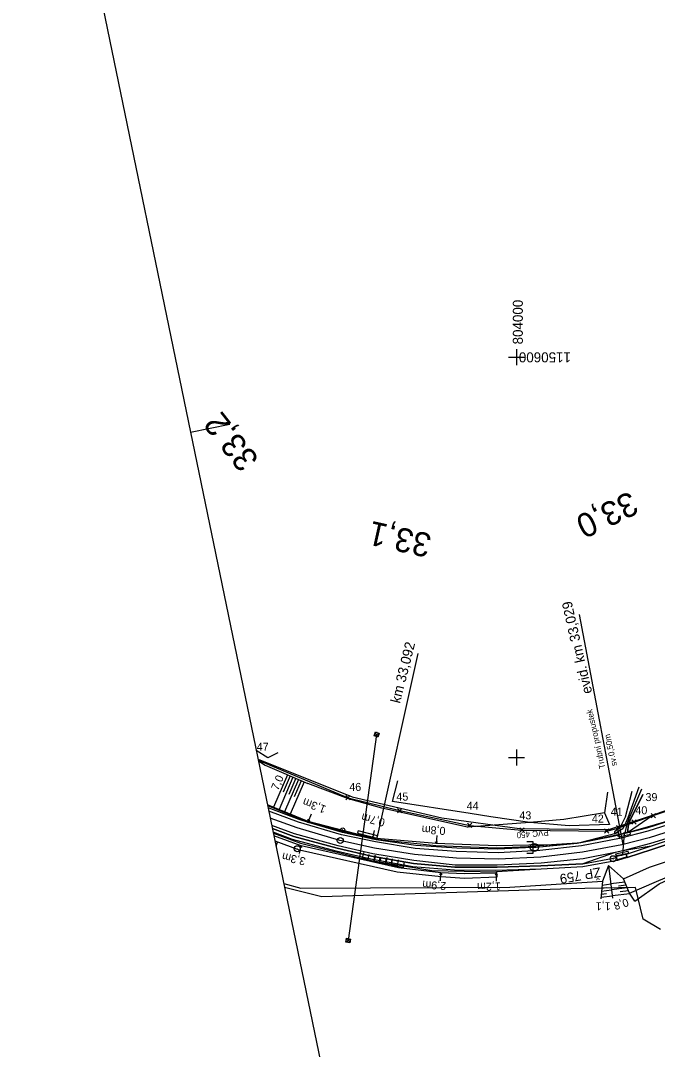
# Model space of a CAD drawing. Extents: x -804166 to -803706, y -1151030 to -1150147.
# Drawn here: x -804123.8 to -803964.8, y -1150773 to -1150515.9 of the extents above; entities that cross this region are included whole.
import ezdxf

# ---------------------------------------------------------------- set-up
doc = ezdxf.new("R2010")
doc.units = 0
for name, color, linetype in [('0381KM032-037P - Vrstva 1', 7, 'Continuous'), ('0381KM032-037P - Vrstva 11', 7, 'Continuous'), ('0381KM032-037P - Vrstva 13', 7, 'Continuous'), ('0381KM032-037P - Vrstva 16', 7, 'Continuous'), ('0381KM032-037P - Vrstva 17', 7, 'Continuous'), ('0381KM032-037P - Vrstva 19', 7, 'Continuous'), ('0381KM032-037P - Vrstva 25', 7, 'Continuous'), ('0381KM032-037P - Vrstva 4', 7, 'Continuous'), ('0381KM032-037P - Vrstva 43', 7, 'Continuous'), ('0381KM032-037P - Vrstva 44', 7, 'Continuous'), ('0381KM032-037P - Vrstva 48', 7, 'Continuous'), ('0381KM032-037P - Vrstva 49', 7, 'Continuous'), ('0381KM032-037P - Vrstva 7', 7, 'Continuous'), ('0381KM032-037P - Vrstva 9', 7, 'Continuous'), ('Default', 7, 'Continuous'), ('formát', 7, 'Continuous'), ('hran DP - hran DP', 7, 'Continuous'), ('krizky_1000 - souradnice', 7, 'Continuous'), ('krizky_1000 - Vrstva 1', 7, 'Continuous'), ('PSR_C2_2_Lomove_body_Vimperk - Vrstva 60', 7, 'Continuous'), ('PSR_C2_2_trasa_Vimperk - Kabelová trasa', 7, 'Continuous'), ('vyt_sit - stávající', 7, 'Continuous')]:
    doc.layers.add(name, color=color, linetype=linetype)

msp = doc.modelspace()

# ---------------------------------------------------------------- linework, layer by layer
at = {"layer": '0381KM032-037P - Vrstva 1'}
msp.add_lwpolyline([(-803901.91, -1150682.6), (-803910.01, -1150690), (-803918.64, -1150696.78), (-803928.04, -1150703.06), (-803937.95, -1150708.69), (-803946.8, -1150712.93), (-803956.66, -1150716.87), (-803966.85, -1150720.1), (-803973.69, -1150721.81), (-803983.51, -1150723.68), (-803993.92, -1150724.91), (-804004.46, -1150725.42), (-804014.95, -1150725.21), (-804025.47, -1150724.25), (-804035.41, -1150722.67), (-804044.08, -1150720.74), (-804054.77, -1150717.61), (-804061.47, -1150715.14)], dxfattribs=at)
at = {"layer": '0381KM032-037P - Vrstva 11'}
for p, q in [((-804034.26, -1150693.99), (-804035.54, -1150694.57)), ((-804034.75, -1150693.8), (-804035.36, -1150694.08)), ((-804034.44, -1150694.48), (-804035.04, -1150694.76)), ((-804041.41, -1150745.38), (-804042.6, -1150746.13)), ((-804041.93, -1150745.26), (-804042.49, -1150745.62)), ((-804041.53, -1150745.9), (-804042.08, -1150746.25))]:
    msp.add_line(p, q, dxfattribs=at)
for points in [[(-804034.6, -1150694.92), (-804035.54, -1150694.57), (-804035.19, -1150693.64), (-804034.25, -1150693.98)], [(-804041.63, -1150746.35), (-804042.61, -1150746.13), (-804042.39, -1150745.16), (-804041.41, -1150745.38)]]:
    msp.add_lwpolyline(points, close=True, dxfattribs=at)
at = {"layer": '0381KM032-037P - Vrstva 13'}
for p, q in [((-804051.27, -1150714.14), (-804052.03, -1150715.99)), ((-804035.82, -1150720.44), (-804051.93, -1150716.22)), ((-804035.5, -1150718.26), (-804035.97, -1150720.21)), ((-804019.87, -1150719.5), (-804020.03, -1150721.49)), ((-804054.2, -1150724.02), (-804053.75, -1150722.07)), ((-803972.34, -1150724.85), (-803974.74, -1150725.59)), ((-803972.54, -1150724.23), (-803972.54, -1150724.26)), ((-803972.54, -1150724.26), (-803972.29, -1150725.01)), ((-803972.34, -1150724.85), (-803972.29, -1150725.01)), ((-803974.7, -1150725.77), (-803974.91, -1150725)), ((-803974.74, -1150725.59), (-803974.7, -1150725.77)), ((-803972.29, -1150725.01), (-803974.7, -1150725.77)), ((-804018.95, -1150730.84), (-804018.83, -1150728.85)), ((-804004.99, -1150728.9), (-804004.87, -1150729.93)), ((-804004.95, -1150730.9), (-804004.99, -1150728.9))]:
    msp.add_line(p, q, dxfattribs=at)
for points in [[(-803902.54, -1150686.99), (-803908.53, -1150691.68), (-803917.54, -1150698.65), (-803926.89, -1150705.06), (-803937, -1150710.49), (-803946.02, -1150714.66), (-803956.26, -1150718.85), (-803966.29, -1150722.19), (-803972.54, -1150724.26)], [(-803972.29, -1150725.01), (-803966.12, -1150722.97), (-803955.96, -1150719.58), (-803945.71, -1150715.38), (-803936.57, -1150711.19), (-803926.51, -1150705.78), (-803917.07, -1150699.31), (-803908.04, -1150692.29), (-803902.09, -1150687.65)], [(-804052.03, -1150715.99), (-804062.15, -1150711.83)], [(-804062.12, -1150712.02), (-804052.3, -1150716.03), (-804051.93, -1150716.22)], [(-804052.11, -1150715.42), (-804052.03, -1150715.99), (-804051.56, -1150715.64)], [(-803991.2, -1150721.8), (-803996.89, -1150721.92), (-804004.84, -1150722.06), (-804020.03, -1150721.49), (-804035.97, -1150720.21), (-804052.03, -1150715.99)], [(-804060.92, -1150717.79), (-804055.61, -1150719.76), (-804044.75, -1150722.66), (-804036.16, -1150724.67), (-804025.7, -1150726.54), (-804015.38, -1150727.38), (-804004.78, -1150727.4), (-803993.85, -1150727.11), (-803983.42, -1150726.57), (-803974.91, -1150725)], [(-803974.7, -1150725.77), (-803983.37, -1150727.37), (-803993.84, -1150727.91), (-804005.29, -1150728.22), (-804015.43, -1150728.15), (-804025.86, -1150727.31), (-804036.32, -1150725.46), (-804045.02, -1150723.43), (-804055.91, -1150720.49), (-804060.73, -1150718.71)], [(-804060.69, -1150718.95), (-804053.9, -1150721.4), (-804036.64, -1150725.7), (-804021.1, -1150728.28), (-804004.99, -1150728.61), (-804004.87, -1150729.93)], [(-804004.99, -1150728.9), (-804013.04, -1150729.07), (-804018.83, -1150728.85), (-804029.4, -1150727.62), (-804053.75, -1150722.07), (-804060.56, -1150719.58)], [(-804036.15, -1150719.65), (-804035.97, -1150720.21), (-804035.56, -1150719.79)], [(-804004.87, -1150729.93), (-804012.98, -1150730.26), (-804018.76, -1150729.81), (-804029.79, -1150728.64), (-804054.15, -1150723.15), (-804060.27, -1150720.94)], [(-804053.57, -1150722.62), (-804053.75, -1150722.07), (-804054.16, -1150722.49)], [(-803991.2, -1150721.8), (-803997.06, -1150722.33), (-804004.97, -1150722.65), (-804020.12, -1150722.09), (-804035.82, -1150720.44)], [(-804020.29, -1150720.97), (-804020.03, -1150721.49), (-804019.69, -1150721.02)], [(-803972.34, -1150724.85), (-803972.34, -1150724.85), (-803972.48, -1150724.42), (-803972.48, -1150724.42), (-803972.54, -1150724.26), (-803972.54, -1150724.23)], [(-803974.74, -1150725.59), (-803974.75, -1150725.58), (-803974.86, -1150725.17), (-803974.86, -1150725.17), (-803974.91, -1150725)], [(-804018.56, -1150729.36), (-804018.83, -1150728.85), (-804019.16, -1150729.33)], [(-804004.68, -1150729.4), (-804004.99, -1150728.9), (-804005.28, -1150729.41)], [(-804004.99, -1150728.9), (-804004.99, -1150728.9), (-804004.99, -1150728.9), (-804004.99, -1150728.61)]]:
    msp.add_lwpolyline(points, dxfattribs=at)
at = {"layer": '0381KM032-037P - Vrstva 16'}
msp.add_line((-803972.81, -1150718.81), (-803972.25, -1150718.74), dxfattribs=at)
for points in [[(-803969.39, -1150707.42), (-803972.15, -1150715.07), (-803972.68, -1150716.27), (-803973.1, -1150717.09), (-803973.4, -1150717.86), (-803975.59, -1150719.16)], [(-803971.15, -1150708.54), (-803972.82, -1150714.95), (-803974.15, -1150717.57), (-803975.48, -1150718.61), (-803975.59, -1150719.16)], [(-803972.81, -1150718.81), (-803972.31, -1150716.69), (-803971.8, -1150715.26), (-803968.63, -1150707.87)], [(-803968.41, -1150709.25), (-803971.62, -1150715.84), (-803971.99, -1150716.8), (-803972.25, -1150718.74)]]:
    msp.add_lwpolyline(points, dxfattribs=at)
at = {"layer": '0381KM032-037P - Vrstva 17'}
for points in [[(-804059.54, -1150698.86), (-804062.04, -1150700.07), (-804064.95, -1150698.29)], [(-803996.63, -1150716.3), (-804006.34, -1150714.83), (-804011.55, -1150713.97), (-804030.97, -1150711.02), (-804029.61, -1150705.83)], [(-803977.22, -1150708.65), (-803977.99, -1150713.83)], [(-803977.99, -1150713.83), (-803976.74, -1150716.79), (-803986.83, -1150717.08), (-803996.63, -1150716.3)]]:
    msp.add_lwpolyline(points, dxfattribs=at)
at = {"layer": '0381KM032-037P - Vrstva 19'}
for p, q in [((-803973.32, -1150721.76), (-803984.23, -1150664.27)), ((-803971.53, -1150718.65), (-803974.65, -1150719.35)), ((-803974.65, -1150719.35), (-803974.64, -1150719.23)), ((-803974.51, -1150719.84), (-803974.65, -1150719.35)), ((-803974.51, -1150719.84), (-803971.47, -1150719.15)), ((-803973.09, -1150718.93), (-803973.51, -1150724.35)), ((-803972.25, -1150718.74), (-803972.81, -1150718.81)), ((-803971.47, -1150719.15), (-803971.53, -1150718.65)), ((-803975.23, -1150724.05), (-803972.11, -1150723.39)), ((-803975.23, -1150724.05), (-803975.1, -1150724.59)), ((-803972.01, -1150723.98), (-803975.1, -1150724.59)), ((-803974.91, -1150725), (-803975.1, -1150724.59)), ((-803974.91, -1150725), (-803974.9, -1150724.64)), ((-803972.11, -1150723.39), (-803972.01, -1150723.98)), ((-803974.91, -1150725), (-803974.91, -1150725))]:
    msp.add_line(p, q, dxfattribs=at)
for points in [[(-803974.64, -1150719.23), (-803973.09, -1150718.93), (-803972.81, -1150718.81)], [(-803975.1, -1150724.59), (-803974.9, -1150724.64), (-803973.51, -1150724.35), (-803972.67, -1150724.15), (-803972.01, -1150723.98)]]:
    msp.add_lwpolyline(points, dxfattribs=at)
for centre, major_axis, ratio, start_param, end_param in [((-803973.07, -1150718.94), (-0.255, -0.028), 0.056503, 4.768181, 7.86041), ((-803973.09, -1150718.94), (-0.255, -0.028), 0.056457, 1.624991, 4.720578), ((-803973.51, -1150724.33), (0.232, 0.091), 0.052847, 1.520766, 4.668999), ((-803973.51, -1150724.33), (0.232, 0.091), 0.052921, 4.661932, 7.811186)]:
    msp.add_ellipse(centre, major_axis=major_axis, ratio=ratio, start_param=start_param, end_param=end_param, dxfattribs=at)
at = {"layer": '0381KM032-037P - Vrstva 25'}
msp.add_line((-804034.9, -1150694.28), (-804042.01, -1150745.75), dxfattribs=at)
at = {"layer": '0381KM032-037P - Vrstva 4'}
msp.add_line((-803966.29, -1150722.19), (-803973.38, -1150723.34), dxfattribs=at)
for points in [[(-803904.89, -1150683), (-803906.52, -1150683.39), (-803911.52, -1150688.07), (-803920.11, -1150694.83), (-803929.41, -1150700.94), (-803939.16, -1150706.21), (-803947.89, -1150710.4), (-803957.6, -1150714.53), (-803967.41, -1150717.64)], [(-803904.89, -1150683), (-803911.05, -1150688.74), (-803919.71, -1150695.38), (-803929.09, -1150701.48), (-803938.79, -1150707.1), (-803947.48, -1150711.34), (-803957.42, -1150715.32), (-803967.18, -1150718.43)], [(-803902.5, -1150685.47), (-803908.94, -1150691.19), (-803917.69, -1150697.99), (-803927.24, -1150704.35), (-803937.2, -1150710.05), (-803946.25, -1150714.3), (-803956.41, -1150718.42), (-803966.45, -1150721.53)], [(-803902.5, -1150685.47), (-803902.54, -1150686.99), (-803908.53, -1150691.68), (-803917.54, -1150698.65), (-803926.89, -1150705.06), (-803937, -1150710.49), (-803946.02, -1150714.66), (-803956.26, -1150718.85), (-803966.29, -1150722.19)], [(-803967.41, -1150717.64), (-803975.82, -1150719.77), (-803983.88, -1150721.36), (-803994.18, -1150722.4), (-804004.64, -1150722.95), (-804014.86, -1150722.69), (-804025.14, -1150721.99), (-804034.98, -1150720.62), (-804043.41, -1150718.77), (-804051.93, -1150716.22), (-804054.24, -1150715.48), (-804062, -1150712.59)], [(-803967.18, -1150718.43), (-803974.22, -1150720.27), (-803983.73, -1150722.13), (-803994.13, -1150723.26), (-804004.52, -1150723.87), (-804015.05, -1150723.54), (-804025.27, -1150722.78), (-804035.17, -1150721.13), (-804043.67, -1150719.32), (-804054.39, -1150716.19), (-804061.83, -1150713.39)], [(-803966.45, -1150721.53), (-803973.38, -1150723.34), (-803975.35, -1150723.79), (-803983.32, -1150725.37), (-803993.82, -1150726.43), (-804004.8, -1150726.96), (-804015.29, -1150726.92), (-804025.6, -1150725.76), (-804035.88, -1150724.11), (-804044.5, -1150722.13), (-804055.4, -1150719.07), (-804061.09, -1150716.98)], [(-803975.35, -1150723.79), (-803983.42, -1150726.57), (-803993.85, -1150727.11), (-804004.78, -1150727.4), (-804015.38, -1150727.38), (-804025.7, -1150726.54), (-804036.16, -1150724.67), (-804044.75, -1150722.66), (-804055.61, -1150719.76), (-804060.92, -1150717.79)]]:
    msp.add_lwpolyline(points, dxfattribs=at)
at = {"layer": '0381KM032-037P - Vrstva 43'}
for points in [[(-803972.71, -1150719.94), (-803974.19, -1150720.21), (-803974.72, -1150717.26), (-803973.25, -1150716.99)], [(-803997.39, -1150721.01), (-803995.89, -1150721.01), (-803995.89, -1150724.01), (-803997.39, -1150724.01)], [(-804035.17, -1150724.55), (-804035.58, -1150726), (-804038.46, -1150725.19), (-804038.06, -1150723.74)], [(-804033.84, -1150725), (-804034.23, -1150726.45), (-804037.12, -1150725.67), (-804036.73, -1150724.22)], [(-804032.32, -1150725.04), (-804032.63, -1150726.51), (-804035.56, -1150725.9), (-804035.26, -1150724.43)], [(-804031.05, -1150725.35), (-804031.24, -1150726.84), (-804034.22, -1150726.45), (-804034.02, -1150724.96)], [(-804029.49, -1150725.62), (-804029.77, -1150727.09), (-804032.72, -1150726.52), (-804032.43, -1150725.05)], [(-804028.05, -1150726.05), (-804028.31, -1150727.53), (-804031.27, -1150727.01), (-804031.01, -1150725.53)]]:
    msp.add_lwpolyline(points, dxfattribs=at)
msp.add_circle((-803995.51, -1150722.5), 1, dxfattribs=at)
at = {"layer": '0381KM032-037P - Vrstva 44'}
msp.add_lwpolyline([(-803995.89, -1150722.51), (-803984.82, -1150721.44), (-803974.46, -1150718.74)], dxfattribs=at)
at = {"layer": '0381KM032-037P - Vrstva 48'}
for p, q in [((-804057.18, -1150704.34), (-804060.65, -1150712.45)), ((-804055.8, -1150704.93), (-804059.26, -1150713.02)), ((-804056.49, -1150704.63), (-804058.22, -1150708.69)), ((-804054.42, -1150705.52), (-804057.88, -1150713.59)), ((-804055.11, -1150705.22), (-804056.84, -1150709.27)), ((-804053.04, -1150706.11), (-804056.49, -1150714.16)), ((-804053.73, -1150705.81), (-804055.46, -1150709.84)), ((-804060.03, -1150722.14), (-804059.67, -1150721.16)), ((-803978.65, -1150732.65), (-803977.48, -1150732.51)), ((-803978.58, -1150731.89), (-803976.4, -1150731.62)), ((-803972.9, -1150731.19), (-803976.4, -1150731.62)), ((-803972.3, -1150732.62), (-803976.22, -1150733.11)), ((-803972.6, -1150731.91), (-803974.46, -1150732.13)), ((-803978.85, -1150734.94), (-803976.04, -1150734.6)), ((-803978.79, -1150734.18), (-803977.46, -1150734.02)), ((-803978.72, -1150733.42), (-803976.22, -1150733.11)), ((-803971.67, -1150734.06), (-803976.04, -1150734.6)), ((-803972, -1150733.34), (-803974.07, -1150733.6))]:
    msp.add_line(p, q, dxfattribs=at)
at = {"layer": '0381KM032-037P - Vrstva 49'}
for p, q in [((-803976.97, -1150726.99), (-803978.5, -1150730.91)), ((-803976.97, -1150726.99), (-803975.97, -1150735.13)), ((-803976.97, -1150726.99), (-803973.24, -1150730.36)), ((-804001.62, -1150732.39), (-803978.5, -1150730.91)), ((-803978.5, -1150730.91), (-803978.89, -1150735.31))]:
    msp.add_line(p, q, dxfattribs=at)
for points in [[(-803984.82, -1150721.44), (-803974.64, -1150719.23), (-803973.09, -1150718.93), (-803972.81, -1150718.81), (-803972.25, -1150718.74), (-803965.21, -1150716.75), (-803957.6, -1150714.53), (-803947.89, -1150710.4), (-803939.16, -1150706.21), (-803931.83, -1150702.12), (-803924.09, -1150697.22), (-803916.61, -1150691.84), (-803910.08, -1150686.51), (-803906.52, -1150683.39), (-803903.6, -1150681.32)], [(-803972.25, -1150718.74), (-803965.84, -1150714.34), (-803956.6, -1150711.22), (-803948.84, -1150707.73), (-803941.39, -1150704.08), (-803932.78, -1150700.06), (-803925.79, -1150694.95), (-803918.15, -1150689.68), (-803911.55, -1150684.9), (-803903.6, -1150681.32)], [(-803902.09, -1150687.65), (-803908.04, -1150692.29), (-803917.07, -1150699.31), (-803926.51, -1150705.78), (-803936.57, -1150711.19), (-803945.71, -1150715.38), (-803955.96, -1150719.58), (-803966.12, -1150722.97), (-803972.29, -1150725.01), (-803974.7, -1150725.77), (-803983.37, -1150727.37), (-803993.84, -1150727.91), (-804004.99, -1150728.61), (-804004.87, -1150729.93), (-804012.98, -1150730.26), (-804018.76, -1150729.81), (-804029.79, -1150728.64), (-804054.15, -1150723.15), (-804060.27, -1150720.94)], [(-803973.24, -1150730.36), (-803966.72, -1150727.46), (-803955.16, -1150723.59), (-803942.54, -1150718.42), (-803927.91, -1150711.46), (-803917.77, -1150704.05), (-803910.65, -1150697.21), (-803903.52, -1150690.49), (-803900.1, -1150686.57)], [(-803970.39, -1150735.93), (-803964.35, -1150731.61), (-803955.1, -1150727.23), (-803941.08, -1150721.95), (-803928.21, -1150715.68), (-803916.07, -1150708.06), (-803913.5, -1150704.53), (-803910.65, -1150697.21)], [(-804064.42, -1150700.87), (-804062.72, -1150701.97), (-804052.08, -1150706.52)], [(-803977.22, -1150708.65), (-803977.99, -1150713.83), (-803988.17, -1150715.55), (-803996.63, -1150716.3), (-804012.18, -1150717.41), (-804033.61, -1150712.69), (-804041.95, -1150710.32), (-804052.08, -1150706.52)], [(-803971.76, -1150733.92), (-803964.99, -1150730.97), (-803955.15, -1150726.85), (-803941.3, -1150721.62), (-803928.58, -1150715.41), (-803917.05, -1150707.62), (-803913.5, -1150704.53)], [(-803972.25, -1150718.74), (-803971.99, -1150716.8), (-803971.62, -1150715.84), (-803968.41, -1150709.25)], [(-804062.15, -1150711.83), (-804052.03, -1150715.99)], [(-803984.82, -1150721.44), (-803991.2, -1150721.8), (-803996.89, -1150721.92), (-804004.84, -1150722.06), (-804020.03, -1150721.49), (-804035.97, -1150720.21), (-804052.03, -1150715.99)], [(-804058.09, -1150731.52), (-804053.81, -1150732.63), (-804001.62, -1150732.39)], [(-803970.39, -1150735.93), (-803971.76, -1150733.92), (-803973.24, -1150730.36)]]:
    msp.add_lwpolyline(points, dxfattribs=at)
at = {"layer": '0381KM032-037P - Vrstva 7'}
msp.add_line((-804043.32, -1150718.13), (-804043.42, -1150718.1), dxfattribs=at)
for centre, radius in [((-804043.37, -1150718.12), 0.5), ((-804043.99, -1150720.76), 0.75)]:
    msp.add_circle(centre, radius, dxfattribs=at)
at = {"layer": '0381KM032-037P - Vrstva 9'}
for p, q in [((-804034.8, -1150720.15), (-804024.5, -1150674.02)), ((-804039.51, -1150718.34), (-804039.66, -1150718.92)), ((-804039.66, -1150718.92), (-804034.81, -1150720.14)), ((-804034.66, -1150719.56), (-804039.51, -1150718.34)), ((-804034.81, -1150720.14), (-804034.66, -1150719.56)), ((-804034.66, -1150719.56), (-804034.52, -1150718.98))]:
    msp.add_line(p, q, dxfattribs=at)
at = {"layer": 'formát'}
for p, q in [((-804123.84, -1150413.06), (-804081.38, -1150618.72)), ((-804081.38, -1150618.72), (-804071.58, -1150616.7)), ((-804081.38, -1150618.72), (-803996.46, -1151030.05))]:
    msp.add_line(p, q, dxfattribs=at)
at = {"layer": 'hran DP - hran DP'}
for p, q in [((-804064.5, -1150700.47), (-804041.05, -1150709.83)), ((-803967.26, -1150714.81), (-803939.84, -1150705.78)), ((-804041.05, -1150709.83), (-804018.63, -1150715.09)), ((-804018.63, -1150715.09), (-803999.22, -1150717.72)), ((-803976.9, -1150717.98), (-803967.26, -1150714.81)), ((-803999.22, -1150717.72), (-803976.9, -1150717.98)), ((-804048.58, -1150734.81), (-804057.89, -1150732.49)), ((-803970.22, -1150732.49), (-803982.91, -1150732.74)), ((-803968.3, -1150740.45), (-803970.22, -1150732.49)), ((-803986.36, -1150732.8), (-804048.58, -1150734.81)), ((-803982.91, -1150732.74), (-803986.36, -1150732.8)), ((-803963.98, -1150743), (-803968.3, -1150740.45))]:
    msp.add_line(p, q, dxfattribs=at)
at = {"layer": 'krizky_1000 - Vrstva 1'}
for points in [[(-804000, -1150598), (-804000, -1150602)], [(-804002, -1150600), (-803998, -1150600)], [(-804000, -1150698), (-804000, -1150702)], [(-804002, -1150700), (-803998, -1150700)]]:
    msp.add_lwpolyline(points, dxfattribs=at)
at = {"layer": 'PSR_C2_2_Lomove_body_Vimperk - Vrstva 60'}
for p, q in [((-804042.6, -1150710.62), (-804041.5, -1150709.52)), ((-804041.5, -1150710.62), (-804042.6, -1150709.52)), ((-804029.69, -1150713.85), (-804028.59, -1150712.75)), ((-804028.59, -1150713.85), (-804029.69, -1150712.75)), ((-803966.35, -1150715.09), (-803965.25, -1150713.99)), ((-803965.25, -1150715.09), (-803966.35, -1150713.99)), ((-804012.21, -1150717.54), (-804011.11, -1150716.44)), ((-804011.11, -1150717.54), (-804012.21, -1150716.44)), ((-803974.96, -1150718.12), (-803973.86, -1150717.02)), ((-803973.86, -1150718.12), (-803974.96, -1150717.02)), ((-803971.16, -1150716.71), (-803970.06, -1150715.61)), ((-803970.06, -1150716.71), (-803971.16, -1150715.61)), ((-803999.15, -1150718.71), (-803998.05, -1150717.61)), ((-803998.05, -1150718.71), (-803999.15, -1150717.61)), ((-803977.97, -1150718.96), (-803976.87, -1150717.86)), ((-803976.87, -1150718.96), (-803977.97, -1150717.86))]:
    msp.add_line(p, q, dxfattribs=at)
at = {"layer": 'PSR_C2_2_trasa_Vimperk - Kabelová trasa'}
msp.add_line((-803965.8, -1150714.54), (-803955.77, -1150711.14), dxfattribs=at)
msp.add_lwpolyline([(-804064.46, -1150700.65), (-804042.05, -1150710.07), (-804029.14, -1150713.3), (-804011.66, -1150716.99), (-803998.6, -1150718.16), (-803977.42, -1150718.41), (-803974.41, -1150717.57), (-803970.61, -1150716.16), (-803965.8, -1150714.54)], dxfattribs=at)
at = {"layer": 'vyt_sit - stávající'}
for p, q in [((-804054.77, -1150722.82), (-804054.67, -1150722.82)), ((-803975.87, -1150725.31), (-803975.77, -1150725.31))]:
    msp.add_line(p, q, dxfattribs=at)
for centre in [(-804054.72, -1150722.82), (-803975.82, -1150725.31)]:
    msp.add_circle(centre, 0.756, dxfattribs=at)

# ---------------------------------------------------------------- texts
at = {"layer": '0381KM032-037P - Vrstva 13'}
for s, rotation, p in [('1,3m', 159.4135, (-804047.36, -1150712.19)), ('0,7m', 165.6438, (-804032.66, -1150715.41)), ('0,8m', 176.7126, (-804017.65, -1150717.4)), ('3,3m', 167.1636, (-804052.49, -1150725.09)), ('2,9m', 176.4791, (-804017.48, -1150731.17)), ('1,2m', 181.2027, (-804003.91, -1150731.23))]:
    msp.add_text(s, height=2, rotation=rotation, dxfattribs=at).set_placement(p)
at = {"layer": '0381KM032-037P - Vrstva 19'}
for s, height, p in [('evid. km 33,029', 2.5, (-803981.04, -1150683.82)), ('Trubní propustek', 1.5, (-803977.75, -1150702.64)), ('sv.0,50m', 1.5, (-803974.83, -1150701.98))]:
    msp.add_text(s, height=height, rotation=102.69, dxfattribs=at).set_placement(p)
at = {"layer": '0381KM032-037P - Vrstva 43'}
msp.add_text('PVC 450', height=1.5, rotation=185, dxfattribs=at).set_placement((-803991.99, -1150718.03))
at = {"layer": '0381KM032-037P - Vrstva 48'}
for s, rotation, p in [('7,0', 66.8248, (-804059.51, -1150708.39)), ('1,1', 179.9545, (-803976.45, -1150736.17)), ('0,8', 197.0064, (-803972.32, -1150735.18))]:
    msp.add_text(s, height=2, rotation=rotation, dxfattribs=at).set_placement(p)
at = {"layer": '0381KM032-037P - Vrstva 7'}
for s, rotation, p in [('33,2', 128.139, (-804064.09, -1150625.46)), ('33,0', 205.6225, (-803971.56, -1150633.32)), ('33,1', 167.4012, (-804020.85, -1150644.28))]:
    msp.add_text(s, height=6, rotation=rotation, dxfattribs=at).set_placement(p)
at = {"layer": '0381KM032-037P - Vrstva 9'}
msp.add_text('km 33,092', height=2.5, rotation=75.8763, dxfattribs=at).set_placement((-804029.06, -1150686.64))
at = {"layer": 'Default'}
for s, p in [('47', (-804064.84, -1150698.32)), ('46', (-804041.73, -1150708.37)), ('45', (-804029.96, -1150710.79)), ('39', (-803967.74, -1150710.91)), ('44', (-804012.4, -1150713.09)), ('43', (-803999.24, -1150715.47)), ('42', (-803981.13, -1150716.29)), ('41', (-803976.44, -1150714.57)), ('40', (-803970.26, -1150714.21))]:
    msp.add_text(s, height=2, dxfattribs=at).set_placement(p)
at = {"layer": 'krizky_1000 - souradnice'}
for s, rotation, p in [('804000', 90, (-803998.38, -1150596.79)), ('1150600', 180, (-803986.36, -1150598.77))]:
    msp.add_text(s, height=2.5, rotation=rotation, dxfattribs=at).set_placement(p)
at = {"layer": 'vyt_sit - stávající'}
msp.add_text('ŽP 759', height=2.4, rotation=190, dxfattribs=at).set_placement((-803979.13, -1150727.45))

doc.saveas('drawing.dxf')
